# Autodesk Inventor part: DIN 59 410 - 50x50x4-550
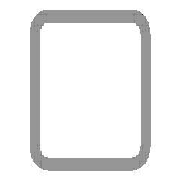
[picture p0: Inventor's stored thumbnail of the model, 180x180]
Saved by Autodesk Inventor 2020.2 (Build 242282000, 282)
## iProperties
Manager: www.cadconsulting.pl
Company: Fabian Stasiak CAD Consulting
Created: 2015-01
Part Number: DIN 59 410 - 50x50x4-550
Material: Stal, miękka
Description: Rurki stalowe o przekroju kwadratowym formowane na gorąco
Document SubType Name: Modellieren
Standard: DIN
Designer: F.Stasiak
Standards Organization: DIN
Language: pl-PL
Size Designation: 50x50x4
Categories: <MemberInstance><Categories><Category DisplayName="Kształtowniki konstrukcyjne" InternalName="089c4875-fa83-4c05-b084-43b9cc11f5ed" Mnemonic="GRDR"><CategoryPar
Stock Number: 50x50x4
Density: 7.85 g/cm^3
Appearance: Częściowo polerowana
Mass: 2999.78 g
Surface Area: 1924.59 cm^2
Volume: 382.138 cm^3
Catalog Web Link: www.expertbooks.pl
_CCFamilyMember: 40
_CCFamilyDisplayName: DIN 59410 (Kwadrat) - Rurki stalowe o przekroju kwadratowym formowane na gorąco
_FrameMemberDoc: Frame Member File
_Version: 15.0.0
_GetPNFromCC: 1
G_W: 50,000 mm
G_H: 50,000 mm
+8FF27FA5-21D4-4638-874B-14D2D73CEF95+CUTDETAIL1: Wytnij
+8F646C4B-5F56-4AE8-B788-BF1B65A28887+CUTDETAIL2: Wytnij
G_L: 550,000 mm
IsCustomPart: 1
Author: F.Stasiak
Subject: Zbiór ćwiczeń. Autodesk Inventor 2020. Kurs Professional
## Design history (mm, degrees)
node "Płaszczyzna początkowa"
node "Płaszczyzna końcowa"
sketch "Szkic"
  geometry: L1 (-17, 25)-(17, 25); L2 (25, 17)-(25, -17); L3 (17, -25)-(-17, -25); L4 (-25, -17)-(-25, 17); L5 (-37.32, 0)-(37.32, 0) reference; L6 (0, -37.32)-(0, 37.32) reference; L7 (-17, 21)-(17, 21); L8 (21, 17)-(21, -17); L9 (17, -21)-(-17, -21); L10 (-21, -17)-(-21, 17); A1 r 8 centre (-17, 17) between (-17, 25) and (-25, 17); A2 r 8 centre (17, 17) between (25, 17) and (17, 25); A3 r 8 centre (17, -17) between (17, -25) and (25, -17); A4 r 8 centre (-17, -17) between (-25, -17) and (-17, -25); A5 r 4 centre (-17, 17) between (-17, 21) and (-21, 17); A6 r 4 centre (17, 17) between (21, 17) and (17, 21); A7 r 4 centre (17, -17) between (17, -21) and (21, -17); A8 r 4 centre (-17, -17) between (-21, -17) and (-17, -21); 3 further points
  constraints: 16 end point, 16 point on circle, 8 centre point, 8 tangent, 6 point on line, 4 parallel, 3 equal radius, 3 perpendicular, 1 horizontal, 7 other
  dimensions: "b" = 50 distance of point (-25, 25) point (25, 25); "msp_r" = 8 radius of A1 (= 2 x ParT); "d8" = 25 distance between parallel lines of L4 L6 (= d9); "d9" = 25 distance between parallel lines of L3 L5 (= 0.5 x b); "d10" = 4 distance between parallel lines of L3 L9 (= ParT)
extrude "Bryła" new body sketch "Szkic" taper "d4" = 0 deg; stored distance "NLG" = 10
node "Driven Length"
  sketch "Sketch2"
    geometry: L1 (0, 0)-(10, 0) reference
    constraints: 2 end point, 1 horizontal
  workplane "Work Plane3"
  sketch "Sketch3"
    geometry: L1 (-2, 25)-(12, 25) reference; L2 (-2, 575)-(12, 575) reference
    dimensions: "d14" = 550 distance between parallel lines of L1 L2 (derived)
node "Płaszczyzna konstrukcyjna4"
feature "Podział1"
node "Płaszczyzna konstrukcyjna5"
feature "Podział2"
body "Solid1"
other parameters: "ParT" = 4, "G_OFFSET_START" = -25 [user parameter; used in 1 equation term], "G_OFFSET_END" = -25 [user parameter; used in 1 equation term], "d11" = 25 (= -G_OFFSET_START), "d12" = 575 (= G_OFFSET_END + B_L), "G_L" = 550 (= d14) [user parameter], "d13" = 90 deg
